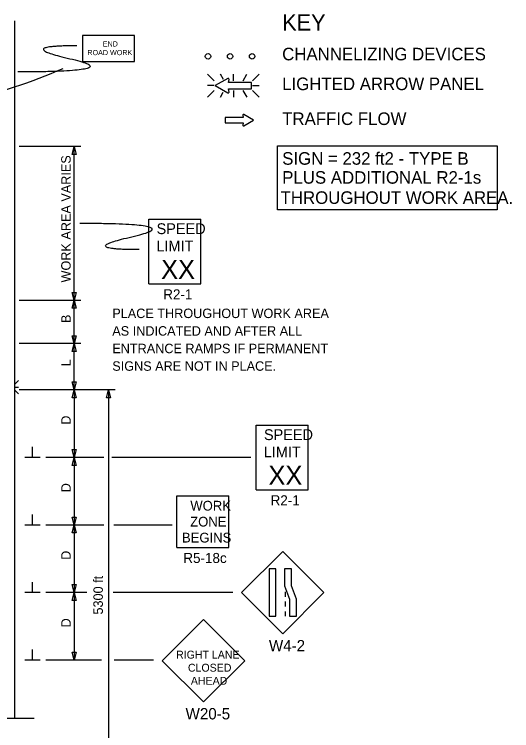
# Model space of a CAD drawing. Extents: x 16774 to 18475, y 7218 to 8206.
# Drawn here: x 17056 to 17424, y 7676 to 8206 of the extents above; entities that cross this region are included whole.
import ezdxf

# ---------------------------------------------------------------- set-up
doc = ezdxf.new("R2010")
doc.units = 0
for name, color, linetype in [('MT_SCRATCH_LEVEL_E', 7, 'Continuous'), ('PAVT_EDGE_EX', 7, 'Continuous'), ('TRAFFIC_SIGNS_PR', 7, 'Continuous'), ('TYPICAL_TEXT_DIMEN_EX', 7, 'Continuous'), ('TYPICAL_TEXT_DIMEN_PR', 7, 'Continuous')]:
    doc.layers.add(name, color=color, linetype=linetype)

msp = doc.modelspace()

# ---------------------------------------------------------------- linework, layer by layer
at = {"layer": 'MT_SCRATCH_LEVEL_E'}
for p, q in [((17232.62, 8127.73), (17225.38, 8131.84)), ((17225.01, 8129.58), (17211.76, 8129.58)), ((17211.76, 8129.58), (17211.76, 8125.84)), ((17224.7, 8131.36), (17225.01, 8129.58)), ((17225.38, 8123.58), (17232.62, 8127.73)), ((17211.76, 8125.84), (17225.01, 8125.84)), ((17225.01, 8125.84), (17224.7, 8124.06))]:
    msp.add_line(p, q, dxfattribs=at)
for centre, start, end in [((17225.16, 8131.43), 60.4248, 189.9638), ((17225.16, 8123.99), 170.0362, 299.7731)]:
    msp.add_arc(centre, 0.463, start, end, dxfattribs=at)
at = {"layer": 'PAVT_EDGE_EX'}
msp.add_line((17056.01, 8201.21), (17056.01, 7684.99), dxfattribs=at)
at = {"layer": 'TRAFFIC_SIGNS_PR'}
for p, q in [((17198.66, 8161.74), (17203.59, 8156.8)), ((17210.42, 8157.91), (17208.21, 8161.74)), ((17217.74, 8156.8), (17217.74, 8161.74)), ((17224.97, 8156.8), (17227.82, 8161.74)), ((17231.89, 8156.8), (17236.83, 8161.74)), ((17203.59, 8153.25), (17198.66, 8153.25)), ((17231.89, 8153.25), (17236.83, 8153.25)), ((17198.66, 8144.76), (17203.59, 8149.69)), ((17208.17, 8144.76), (17210.28, 8148.42)), ((17217.74, 8149.69), (17217.74, 8144.76)), ((17227.87, 8144.76), (17225.02, 8149.69)), ((17231.89, 8149.69), (17236.83, 8144.75)), ((17155.21, 8054.55), (17193.61, 8054.55)), ((17155.21, 8006.55), (17155.21, 8054.55)), ((17193.61, 8006.55), (17193.61, 8054.55)), ((17155.21, 8006.55), (17193.61, 8006.55)), ((17055.99, 7932.21), (17058.81, 7935.03)), ((17055.99, 7930.18), (17058.81, 7930.18)), ((17055.99, 7928.14), (17058.81, 7925.32)), ((17234.61, 7902.14), (17273.01, 7902.14)), ((17234.61, 7854.14), (17234.61, 7902.14)), ((17273.01, 7854.14), (17273.01, 7902.14)), ((17234.61, 7854.14), (17273.01, 7854.14)), ((17175.93, 7811.44), (17175.93, 7849.84)), ((17175.93, 7849.84), (17214.33, 7849.84)), ((17214.33, 7811.44), (17214.33, 7849.84)), ((17175.93, 7811.44), (17214.33, 7811.44)), ((17254.21, 7808.63), (17223.66, 7778.08)), ((17284.75, 7778.08), (17254.21, 7808.63)), ((17223.66, 7778.08), (17254.21, 7747.53)), ((17254.21, 7747.53), (17284.75, 7778.08)), ((17256.05, 7778.63), (17256.05, 7775.03)), ((17256.05, 7771.43), (17256.05, 7767.83)), ((17256.05, 7764.23), (17256.05, 7760.63)), ((17195.71, 7758.26), (17165.16, 7727.71)), ((17226.26, 7727.71), (17195.71, 7758.26)), ((17165.16, 7727.71), (17195.71, 7697.17)), ((17195.71, 7697.17), (17226.26, 7727.71))]:
    msp.add_line(p, q, dxfattribs=at)
for points in [[(17106.17, 8171.09), (17144.57, 8171.09), (17144.57, 8190.29), (17106.17, 8190.29)], [(17244.2, 7795.78), (17244.2, 7760.63), (17249.26, 7760.63), (17249.26, 7795.78)], [(17255.6, 7795.78), (17255.6, 7783.2), (17259.37, 7773.21), (17259.37, 7760.63), (17264.42, 7760.63), (17264.42, 7773.21), (17260.66, 7783.2), (17260.66, 7795.78)]]:
    msp.add_lwpolyline(points, close=True, dxfattribs=at)
for points in [[(17213.67, 8158.52), (17204.38, 8153.25), (17213.67, 8147.93)], [(17214.54, 8148.55), (17214.14, 8150.82), (17231.15, 8150.82), (17231.15, 8155.62), (17214.14, 8155.62), (17214.55, 8157.9)]]:
    msp.add_lwpolyline(points, dxfattribs=at)
for centre in [(17199, 8174.93), (17215.3, 8174.93), (17231.6, 8174.93)]:
    msp.add_circle(centre, 2, dxfattribs=at)
for centre, radius, start, end in [((16942.96, 8500.8), 366.4, 269.9454, 293.9907), ((17213.96, 8158), 0.598, 350.7308, 118.8916), ((17213.95, 8148.45), 0.597, 241.4833, 9.9593)]:
    msp.add_arc(centre, radius, start, end, dxfattribs=at)
for points in [[(17102.08, 8182.76), (17054.84, 8182.76), (17139.86, 8163.41), (17058.38, 8163.41)], [(17147.97, 8031.91), (17100.74, 8031.91), (17185.76, 8051.25), (17104.28, 8051.25)]]:
    msp.add_open_spline(points, degree=2, dxfattribs=at)
at = {"layer": 'TYPICAL_TEXT_DIMEN_EX'}
msp.add_lwpolyline([(17250.4, 8108.78), (17412.75, 8108.78), (17412.75, 8061.27), (17250.4, 8061.27)], close=True, dxfattribs=at)
at = {"layer": 'TYPICAL_TEXT_DIMEN_PR'}
for p, q in [((17105.01, 8108.12), (17059.31, 8108.12)), ((17098.44, 8102.26), (17100.01, 8108.12)), ((17100.01, 7994.39), (17100.01, 8108.12)), ((17100.01, 8108.12), (17101.58, 8102.26)), ((17100.01, 8102.26), (17098.44, 8102.26)), ((17101.58, 8102.26), (17100.01, 8102.26)), ((17100.01, 7994.39), (17098.44, 8000.25)), ((17098.44, 8000.25), (17100.01, 8000.25)), ((17100.01, 8000.25), (17101.58, 8000.25)), ((17101.58, 8000.25), (17100.01, 7994.39)), ((17105.01, 7994.39), (17059.31, 7994.39)), ((17098.44, 7988.53), (17100.01, 7994.39)), ((17100.01, 7962.33), (17100.01, 7994.39)), ((17100.01, 7994.39), (17101.58, 7988.53)), ((17100.01, 7988.53), (17098.44, 7988.53)), ((17101.58, 7988.53), (17100.01, 7988.53)), ((17100.01, 7962.33), (17098.44, 7968.2)), ((17098.44, 7968.2), (17100.01, 7968.2)), ((17100.01, 7968.2), (17101.58, 7968.2)), ((17101.58, 7968.2), (17100.01, 7962.33)), ((17105.01, 7962.33), (17059.31, 7962.33)), ((17098.44, 7956.47), (17100.01, 7962.33)), ((17100.01, 7928.14), (17100.01, 7962.33)), ((17100.01, 7962.33), (17101.58, 7956.47)), ((17100.01, 7956.47), (17098.44, 7956.47)), ((17101.58, 7956.47), (17100.01, 7956.47)), ((17100.01, 7928.14), (17098.44, 7934)), ((17098.44, 7934), (17100.01, 7934)), ((17100.01, 7934), (17101.58, 7934)), ((17101.58, 7934), (17100.01, 7928.14)), ((17130.44, 7928.14), (17059.31, 7928.14)), ((17098.44, 7922.28), (17100.01, 7928.14)), ((17100.01, 7928.14), (17100.01, 7878.14)), ((17100.01, 7928.14), (17101.58, 7922.28)), ((17123.87, 7922.28), (17125.44, 7928.14)), ((17125.44, 7928.14), (17125.44, 7628.14)), ((17125.44, 7928.14), (17127.01, 7922.28)), ((17100.01, 7922.28), (17098.44, 7922.28)), ((17101.58, 7922.28), (17100.01, 7922.28)), ((17125.44, 7922.28), (17123.87, 7922.28)), ((17127.01, 7922.28), (17125.44, 7922.28)), ((17069.13, 7878.14), (17069.13, 7885.93)), ((17100.01, 7878.14), (17098.44, 7884)), ((17098.44, 7884), (17100.01, 7884)), ((17100.01, 7884), (17101.58, 7884)), ((17101.58, 7884), (17100.01, 7878.14)), ((17074.76, 7878.14), (17063.51, 7878.14)), ((17121.98, 7878.14), (17079.01, 7878.14)), ((17098.44, 7872.28), (17100.01, 7878.14)), ((17100.01, 7878.14), (17100.01, 7828.14)), ((17100.01, 7878.14), (17101.58, 7872.28)), ((17230.76, 7878.14), (17127.93, 7878.14)), ((17100.01, 7872.28), (17098.44, 7872.28)), ((17101.58, 7872.28), (17100.01, 7872.28)), ((17069.13, 7828.14), (17069.13, 7835.93)), ((17100.01, 7828.14), (17098.44, 7834)), ((17098.44, 7834), (17100.01, 7834)), ((17100.01, 7834), (17101.58, 7834)), ((17101.58, 7834), (17100.01, 7828.14)), ((17074.76, 7828.14), (17063.51, 7828.14)), ((17121.96, 7828.14), (17079.01, 7828.14)), ((17098.44, 7822.28), (17100.01, 7828.14)), ((17100.01, 7828.14), (17100.01, 7778.14)), ((17100.01, 7828.14), (17101.58, 7822.28)), ((17172.55, 7828.14), (17129.24, 7828.14)), ((17100.01, 7822.28), (17098.44, 7822.28)), ((17101.58, 7822.28), (17100.01, 7822.28)), ((17069.13, 7778.14), (17069.13, 7785.93)), ((17100.01, 7778.14), (17098.44, 7784)), ((17098.44, 7784), (17100.01, 7784)), ((17100.01, 7784), (17101.58, 7784)), ((17101.58, 7784), (17100.01, 7778.14)), ((17074.76, 7778.14), (17063.51, 7778.14)), ((17109.45, 7778.14), (17079.01, 7778.14)), ((17098.44, 7772.28), (17100.01, 7778.14)), ((17100.01, 7778.14), (17100.01, 7728.14)), ((17100.01, 7778.14), (17101.58, 7772.28)), ((17217.4, 7778.14), (17128.92, 7778.14)), ((17100.01, 7772.28), (17098.44, 7772.28)), ((17101.58, 7772.28), (17100.01, 7772.28)), ((17069.13, 7728.14), (17069.13, 7735.93)), ((17100.01, 7728.14), (17098.44, 7734)), ((17098.44, 7734), (17100.01, 7734)), ((17100.01, 7734), (17101.58, 7734)), ((17101.58, 7734), (17100.01, 7728.14)), ((17074.76, 7728.14), (17063.51, 7728.14)), ((17120.17, 7728.14), (17079.01, 7728.14)), ((17158.6, 7728.14), (17129.63, 7728.14)), ((17070.34, 7684.99), (17008, 7684.99))]:
    msp.add_line(p, q, dxfattribs=at)

# ---------------------------------------------------------------- texts
at = {"layer": 'TRAFFIC_SIGNS_PR'}
for s, height, p in [('END', 3.831, (17121.17, 8182.22)), ('ROAD WORK', 3.831, (17109.78, 8175.83)), ('SPEED', 8, (17160.98, 8043.41)), ('LIMIT', 8, (17160.82, 8030.61)), ('XX', 14.031, (17164.33, 8010.3)), ('R2-1', 7.44, (17165.89, 7995.11)), ('PLACE THROUGHOUT WORK AREA', 7, (17128.21, 7981.27)), ('AS INDICATED AND AFTER ALL', 7, (17128.21, 7968.27)), ('ENTRANCE RAMPS IF PERMANENT', 7, (17128.21, 7955.27)), ('SIGNS ARE NOT IN PLACE.', 7, (17128.21, 7942.27)), ('SPEED', 8, (17240.38, 7891)), ('LIMIT', 8, (17240.22, 7878.2)), ('XX', 14.031, (17243.72, 7857.9)), ('WORK', 7.217, (17185.93, 7838.81)), ('R2-1', 7.44, (17245.29, 7842.7)), ('ZONE', 7.217, (17185.81, 7827)), ('BEGINS', 7.217, (17179.74, 7815.19)), ('R5-18c', 7.44, (17180.74, 7800.01)), ('W4-2', 8.37, (17244.04, 7734.66)), ('RIGHT LANE', 5.85, (17175.37, 7729.28)), ('CLOSED', 5.85, (17184.14, 7719.61)), ('AHEAD', 5.85, (17186.33, 7709.93)), ('W20-5', 8.37, (17182.41, 7684.3))]:
    msp.add_text(s, height=height, dxfattribs=at).set_placement(p)
at = {"layer": 'TYPICAL_TEXT_DIMEN_EX'}
for s, height, p in [('KEY', 12, (17253.84, 8194.04)), ('CHANNELIZING DEVICES', 9.3, (17253.84, 8171.99)), ('LIGHTED ARROW PANEL', 9.3, (17253.84, 8149.94)), ('TRAFFIC FLOW', 9.3, (17253.84, 8124.14)), ('SIGN = 232 ft2 - TYPE B', 9.3, (17253.84, 8094.74)), ('PLUS ADDITIONAL R2-1s', 9.3, (17253.86, 8080.7)), ('THROUGHOUT WORK AREA.', 9.3, (17252.65, 8065.76))]:
    msp.add_text(s, height=height, dxfattribs=at).set_placement(p)
at = {"layer": 'TYPICAL_TEXT_DIMEN_PR'}
for s, p in [('WORK AREA VARIES', (17097.45, 8007.61)), ('B', (17097.45, 7977.6)), ('L', (17097.45, 7945.63)), ('D', (17097.45, 7902.36)), ('D', (17097.45, 7852.36)), ('D', (17097.45, 7802.36)), ('5300 ft', (17121.24, 7761.87)), ('D', (17097.45, 7752.36))]:
    msp.add_text(s, height=7, rotation=90, dxfattribs=at).set_placement(p)

doc.saveas('drawing.dxf')
